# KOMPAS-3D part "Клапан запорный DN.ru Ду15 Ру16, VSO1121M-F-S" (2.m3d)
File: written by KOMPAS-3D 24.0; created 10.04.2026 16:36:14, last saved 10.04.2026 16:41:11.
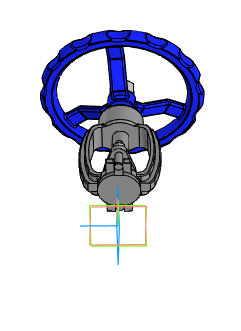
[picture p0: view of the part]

Document properties: Автор: R2D2; Полное имя файла: E:\Работа\Зайцев\VSO3131M-F-S Клапан запорный DN.ru Ду15-100 Ру16\DN15\исходные материалы\2.m3d

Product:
- Component [assembly]: Сборка  | qty 1  | pos. 1  | Масса: 0.728984; Автор: R2D2; source file: dn15_3d_step.a3d
- Body: Тело 1  | qty 1
    Масса: 0.715787
- Component [standard]: Фланец 15-1-01-1-B-ВЧ40-I-dв 19 ГОСТ 33259-2015  | qty 1  | Раздел спецификации: Стандартные изделия; additional columns: BOSimple***Material:38d6725a-5efe-48e1-b177-a7817acb862a
- Part/product: Клапан запорный DN.ru Ду15 Ру16  | designation VSO1121M-F-S
    Масса: 3.1
    Раздел спецификации: Прочие изделия
    Примечание: D090-01942

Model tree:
1. Эскиз:1
2. Элемент выдавливания:1  (labels: Грань.Твердое тело1)
     Расстояние 1 = 25.9987; Смещение 1 = 1
3. Эскиз:2  (with: Ребро.Элемент выдавливания:1)
4. Элемент выдавливания:2
     Расстояние 1 = 500
5. Эскиз:3
6. Элемент выдавливания:3
     Расстояние 1 = 500
7. Эскиз:4  (with: Вершина.Элемент выдавливания:1)
8. Элемент вращения:1  (with: Грань.Элемент выдавливания:1)  (labels: Грань.Твердое тело1; Твердое тело1; Solid1)
     Угол 1 = 360; Расстояние = 40

Referenced files in E:\Работа\Зайцев\VSO3131M-F-S Клапан запорный DN.ru Ду15-100 Ру16\DN15\исходные материалы\: dn15_3d_step.a3d
Referenced files in C:\Program Files\ASCON\KOMPAS-3D v24\Libs\PolynomLib\DATA\vault\Methods\Kompas\3D\: PLib_Flange_GOST_33259_1401.m3d
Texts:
  BOSimple***Material:38d6725a-5efe-48e1-b177-a7817acb862a
  BOSimple***PART:3f5f0d7e-d4da-47dc-6145-6a7f26b7079a***SHORTLOC:B6A6_23E38AE8DB154823[I;1;Круглый;15;1;19;0;ВЧ40 ГОСТ 7293-85]
  VSO1121M-F-S
  DN15
  GOST 26.020 Pr3
  PN40
  ВЧ40 ГОСТ 7293-85
  Ch34
  Ось Z.Начало координат
  Ось Y.Начало координат
  Плоскость ZX.Начало координат
  Plane ZX. Origin
  Плоскость ZY.Начало координат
